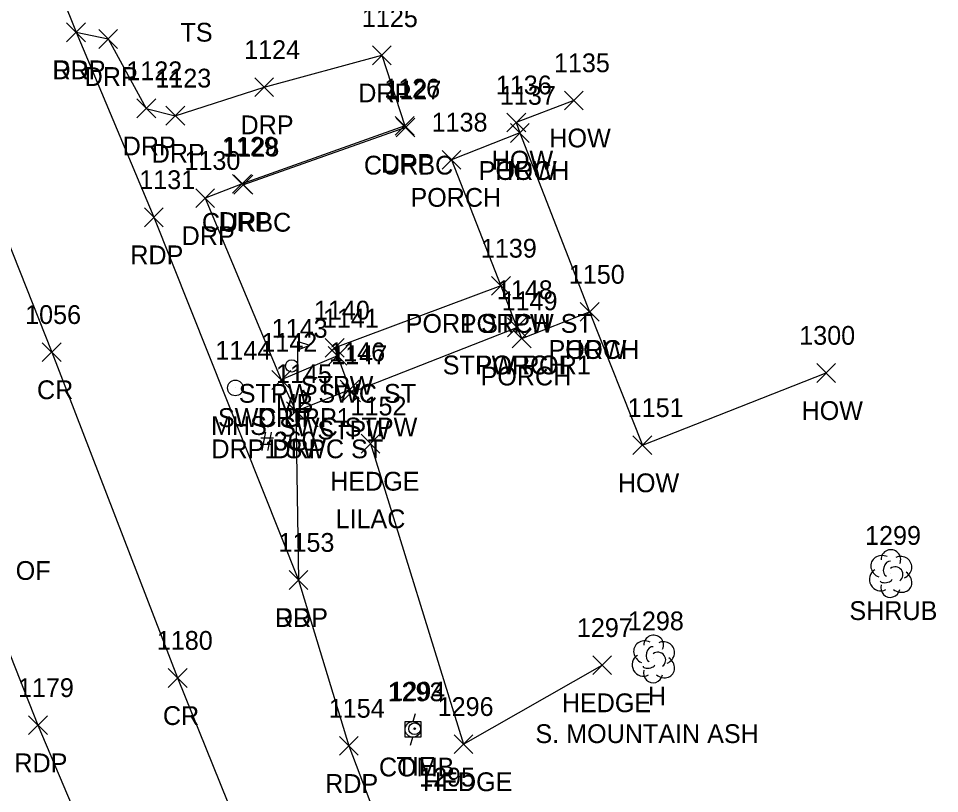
# Model space of a CAD drawing. Extents: x 1651305 to 1654558, y 539481 to 548441.
# Drawn here: x 1654172 to 1654270.1, y 544999.6 to 545082.1 of the extents above; entities that cross this region are included whole.
import ezdxf

# ---------------------------------------------------------------- set-up
doc = ezdxf.new("R2010")
doc.units = 0
for name, color, linetype in [('C_A', 7, 'Continuous'), ('C_C', 7, 'Continuous'), ('C_I', 7, 'Continuous'), ('CBP', 7, 'Continuous'), ('L_A', 7, 'Continuous'), ('L_C', 7, 'Continuous'), ('L_I', 7, 'Continuous'), ('L_TIC', 7, 'Continuous'), ('LAHR', 7, 'Continuous'), ('LBC', 7, 'Continuous'), ('LBF', 7, 'Continuous'), ('LMB', 7, 'Continuous'), ('LSH', 7, 'Continuous'), ('LTD', 7, 'Continuous'), ('P_A', 7, 'Continuous'), ('P_I', 7, 'Continuous'), ('P_TIC', 7, 'Continuous'), ('PET', 7, 'Continuous'), ('PRC', 7, 'Continuous'), ('R_A', 7, 'Continuous'), ('R_I', 7, 'Continuous'), ('R_TIC', 7, 'Continuous'), ('RC', 7, 'Continuous'), ('RDP', 7, 'Continuous'), ('RSW', 7, 'Continuous'), ('S_I', 7, 'Continuous'), ('U_A', 7, 'Continuous'), ('U_I', 7, 'Continuous'), ('UP', 7, 'Continuous'), ('USMH', 7, 'Continuous')]:
    doc.layers.add(name, color=color, linetype=linetype)

msp = doc.modelspace()

# ---------------------------------------------------------------- linework, layer by layer
at = {"layer": 'CBP'}
for radius in [0.625, 0.0833]:
    msp.add_circle((1654214.186, 545006.539), radius, dxfattribs=at)
at = {"layer": 'L_TIC'}
for points in [[(1654230.14, 545072.4), (1654232.14, 545074.4)], [(1654232.14, 545072.4), (1654230.14, 545074.4)], [(1654224.01, 545070.043), (1654226.01, 545072.043)], [(1654226.01, 545070.043), (1654224.01, 545072.043)], [(1654224.388, 545068.937), (1654226.388, 545070.937)], [(1654226.388, 545068.937), (1654224.388, 545070.937)], [(1654224.388, 545068.937), (1654226.388, 545070.937)], [(1654226.388, 545068.937), (1654224.388, 545070.937)], [(1654217.12, 545066.08), (1654219.12, 545068.08)], [(1654219.12, 545066.08), (1654217.12, 545068.08)], [(1654222.373, 545052.669), (1654224.373, 545054.669)], [(1654224.373, 545052.669), (1654222.373, 545054.669)], [(1654222.373, 545052.669), (1654224.373, 545054.669)], [(1654224.373, 545052.669), (1654222.373, 545054.669)], [(1654231.811, 545049.893), (1654233.811, 545051.893)], [(1654233.811, 545049.893), (1654231.811, 545051.893)], [(1654231.811, 545049.893), (1654233.811, 545051.893)], [(1654233.811, 545049.893), (1654231.811, 545051.893)], [(1654224.057, 545048.25), (1654226.057, 545050.25)], [(1654226.057, 545048.25), (1654224.057, 545050.25)], [(1654224.057, 545048.25), (1654226.057, 545050.25)], [(1654226.057, 545048.25), (1654224.057, 545050.25)], [(1654224.58, 545047.071), (1654226.58, 545049.071)], [(1654226.58, 545047.071), (1654224.58, 545049.071)], [(1654204.682, 545046.082), (1654206.682, 545048.082)], [(1654206.682, 545046.082), (1654204.682, 545048.082)], [(1654204.985, 545045.226), (1654206.985, 545047.226)], [(1654206.985, 545045.226), (1654204.985, 545047.226)], [(1654256.976, 545043.395), (1654258.976, 545045.395)], [(1654258.976, 545043.395), (1654256.976, 545045.395)], [(1654206.28, 545041.642), (1654208.28, 545043.642)], [(1654208.28, 545041.642), (1654206.28, 545043.642)], [(1654206.439, 545041.33), (1654208.439, 545043.33)], [(1654208.439, 545041.33), (1654206.439, 545043.33)], [(1654208.495, 545035.878), (1654210.495, 545037.878)], [(1654210.495, 545035.878), (1654208.495, 545037.878)], [(1654237.423, 545035.708), (1654239.423, 545037.708)], [(1654239.423, 545035.708), (1654237.423, 545037.708)], [(1654233.148, 545012.3), (1654235.148, 545014.3)], [(1654235.148, 545012.3), (1654233.148, 545014.3)], [(1654218.387, 545003.9), (1654220.387, 545005.9)], [(1654220.387, 545003.9), (1654218.387, 545005.9)]]:
    msp.add_lwpolyline(points, dxfattribs=at)
at = {"layer": 'LAHR'}
msp.add_lwpolyline([(1654209.495, 545036.878), (1654219.387, 545004.9), (1654234.148, 545013.3)], dxfattribs=at)
at = {"layer": 'LBC'}
msp.add_lwpolyline([(1654231.14, 545073.4), (1654225.01, 545071.043), (1654225.388, 545069.937), (1654232.811, 545050.893), (1654238.423, 545036.708), (1654257.976, 545044.395)], dxfattribs=at)
at = {"layer": 'LBF'}
for points in [[(1654225.388, 545069.937), (1654218.12, 545067.08), (1654223.373, 545053.669), (1654225.057, 545049.25), (1654225.58, 545048.071), (1654232.811, 545050.893)], [(1654223.373, 545053.669), (1654205.682, 545047.082), (1654205.985, 545046.226), (1654207.28, 545042.642), (1654207.439, 545042.33), (1654225.057, 545049.25)]]:
    msp.add_lwpolyline(points, dxfattribs=at)
at = {"layer": 'LMB'}
for p, q in [((1654201.754, 545047.746), (1654203.048, 545047.364)), ((1654201.76, 545045.154), (1654201.759, 545047.748)), ((1654201.759, 545046.846), (1654203.042, 545047.355)), ((1654201.104, 545045.145), (1654201.104, 545045.145))]:
    msp.add_line(p, q, dxfattribs=at)
msp.add_circle((1654201.104, 545045.145), 0.656, dxfattribs=at)
at = {"layer": 'LSH'}
msp.add_line((1654264.824, 545023.109), (1654264.824, 545023.109), dxfattribs=at)
msp.add_line((1654264.824, 545023.109), (1654264.824, 545023.109), dxfattribs=at)
msp.add_arc((1654264.871, 545024.543), 1.047, 335.52715, 180.95627, dxfattribs=at)
for centre, major_axis, ratio, start_param, end_param in [((1654264.032, 545023.775), (1.21, -0.512), 0.895232, 1.570796, 4.712389), ((1654265.866, 545023.692), (-1.141, -0.483), 0.949671, 1.570796, 4.712389), ((1654264.616, 545023.567), (-0.208, -0.792), 0.645439, 3.141593, 6.283185), ((1654265.324, 545022.942), (-0.5, 0.667), 0.989748, 3.141593, 6.283185), ((1654263.741, 545022.4), (0.584, -1.042), 0.959034, 3.141593, 6.283185), ((1654265.824, 545022.276), (-1.09, 0.792), 0.841452, 1.570796, 4.712389), ((1654264.824, 545021.609), (0.265, 1.061), 0.942809, 1.570796, 4.712389), ((1654264.366, 545022.359), (-0.625, -0.083), 0.423636, 0, 3.141593)]:
    msp.add_ellipse(centre, major_axis=major_axis, ratio=ratio, start_param=start_param, end_param=end_param, dxfattribs=at)
at = {"layer": 'LTD'}
msp.add_line((1654239.578, 545014.017), (1654239.578, 545014.017), dxfattribs=at)
msp.add_line((1654239.578, 545014.017), (1654239.578, 545014.017), dxfattribs=at)
msp.add_arc((1654239.625, 545015.451), 1.047, 335.52715, 180.95627, dxfattribs=at)
for centre, major_axis, ratio, start_param, end_param in [((1654238.786, 545014.683), (1.21, -0.512), 0.895232, 1.570796, 4.712389), ((1654240.62, 545014.6), (-1.141, -0.483), 0.949671, 1.570796, 4.712389), ((1654239.37, 545014.475), (-0.208, -0.792), 0.645439, 3.141593, 6.283185), ((1654240.078, 545013.85), (-0.5, 0.667), 0.989748, 3.141593, 6.283185), ((1654238.495, 545013.308), (0.584, -1.042), 0.959034, 3.141593, 6.283185), ((1654240.578, 545013.183), (-1.09, 0.792), 0.841452, 1.570796, 4.712389), ((1654239.12, 545013.266), (-0.625, -0.083), 0.423636, 0, 3.141593), ((1654239.578, 545012.517), (0.265, 1.061), 0.942809, 1.570796, 4.712389)]:
    msp.add_ellipse(centre, major_axis=major_axis, ratio=ratio, start_param=start_param, end_param=end_param, dxfattribs=at)
at = {"layer": 'P_TIC'}
for points in [[(1654177.155, 545079.649), (1654179.155, 545081.649)], [(1654179.155, 545079.649), (1654177.155, 545081.649)], [(1654185.439, 545059.962), (1654187.439, 545061.962)], [(1654187.439, 545059.962), (1654185.439, 545061.962)], [(1654174.565, 545045.61), (1654176.565, 545047.61)], [(1654176.565, 545045.61), (1654174.565, 545047.61)], [(1654200.827, 545021.365), (1654202.827, 545023.365)], [(1654202.827, 545021.365), (1654200.827, 545023.365)], [(1654187.965, 545010.94), (1654189.965, 545012.94)], [(1654189.965, 545010.94), (1654187.965, 545012.94)], [(1654173.104, 545005.911), (1654175.104, 545007.911)], [(1654175.104, 545005.911), (1654173.104, 545007.911)], [(1654206.176, 545003.715), (1654208.176, 545005.715)], [(1654208.176, 545003.715), (1654206.176, 545005.715)]]:
    msp.add_lwpolyline(points, dxfattribs=at)
at = {"layer": 'PET'}
for points in [[(1654139.13, 545176.501), (1654150.393, 545147.194), (1654157.161, 545131.709), (1654170.764, 545099.134), (1654178.155, 545080.649), (1654186.439, 545060.962), (1654201.827, 545022.365), (1654207.176, 545004.715), (1654219.138, 544973.235), (1654242.36, 544920.072), (1654247.532, 544907.575), (1654259.279, 544878.108), (1654268.455, 544853.759), (1654271.522, 544840.232), (1654282.762, 544813.426), (1654295.449, 544782.265), (1654306.751, 544753.721), (1654320.353, 544717.464), (1654325.712, 544702.64)], [(1654112.873, 545166.538), (1654122.035, 545140.208), (1654132.622, 545111.941), (1654135.362, 545108.194), (1654138.441, 545103.483), (1654151.391, 545069.682), (1654150.584, 545065.43), (1654160.56, 545041.116), (1654174.104, 545006.911), (1654181.292, 544989.927), (1654184.888, 544987.01), (1654195.032, 544961.541), (1654207.758, 544928.164), (1654222.993, 544890.413), (1654239.031, 544850.694), (1654252.069, 544818.679), (1654270.718, 544773.03), (1654287.358, 544732.427), (1654297.759, 544708.463), (1654313.88, 544667.099), (1654319.767, 544684.597), (1654325.712, 544702.64)]]:
    msp.add_lwpolyline(points, dxfattribs=at)
at = {"layer": 'PRC'}
msp.add_lwpolyline([(1654126.316, 545171.737), (1654141.33, 545133.412), (1654151.931, 545107.487), (1654165.206, 545072.693), (1654175.565, 545046.61), (1654188.965, 545011.94), (1654198.023, 544989.456), (1654207.449, 544965.611), (1654220.746, 544933.068), (1654235.659, 544895.022), (1654251.308, 544856.189), (1654265.059, 544822.156), (1654283.023, 544778.205), (1654298.758, 544737.492), (1654308.597, 544712.81), (1654319.767, 544684.597)], dxfattribs=at)
at = {"layer": 'R_TIC'}
for points in [[(1654177.155, 545079.649), (1654179.155, 545081.649)], [(1654179.155, 545079.649), (1654177.155, 545081.649)], [(1654180.582, 545078.938), (1654182.582, 545080.938)], [(1654182.582, 545078.938), (1654180.582, 545080.938)], [(1654209.702, 545077.198), (1654211.702, 545079.198)], [(1654211.702, 545077.198), (1654209.702, 545079.198)], [(1654197.172, 545073.799), (1654199.172, 545075.799)], [(1654199.172, 545073.799), (1654197.172, 545075.799)], [(1654184.63, 545071.551), (1654186.63, 545073.551)], [(1654186.63, 545071.551), (1654184.63, 545073.551)], [(1654187.718, 545070.771), (1654189.718, 545072.771)], [(1654189.718, 545070.771), (1654187.718, 545072.771)], [(1654212.13, 545069.697), (1654214.13, 545071.697)], [(1654214.13, 545069.697), (1654212.13, 545071.697)], [(1654212.208, 545069.511), (1654214.208, 545071.511)], [(1654214.208, 545069.511), (1654212.208, 545071.511)], [(1654194.821, 545063.514), (1654196.821, 545065.514)], [(1654196.821, 545063.514), (1654194.821, 545065.514)], [(1654194.963, 545063.43), (1654196.963, 545065.43)], [(1654196.963, 545063.43), (1654194.963, 545065.43)], [(1654190.905, 545062.004), (1654192.905, 545064.004)], [(1654192.905, 545062.004), (1654190.905, 545064.004)], [(1654190.905, 545062.004), (1654192.905, 545064.004)], [(1654192.905, 545062.004), (1654190.905, 545064.004)], [(1654204.985, 545045.226), (1654206.985, 545047.226)], [(1654206.985, 545045.226), (1654204.985, 545047.226)], [(1654198.997, 545042.652), (1654200.997, 545044.652)], [(1654200.997, 545042.652), (1654198.997, 545044.652)], [(1654198.997, 545042.652), (1654200.997, 545044.652)], [(1654200.997, 545042.652), (1654198.997, 545044.652)], [(1654206.28, 545041.642), (1654208.28, 545043.642)], [(1654208.28, 545041.642), (1654206.28, 545043.642)], [(1654200.561, 545039.322), (1654202.561, 545041.322)], [(1654202.561, 545039.322), (1654200.561, 545041.322)], [(1654200.561, 545039.322), (1654202.561, 545041.322)], [(1654202.561, 545039.322), (1654200.561, 545041.322)], [(1654200.827, 545021.365), (1654202.827, 545023.365)], [(1654202.827, 545021.365), (1654200.827, 545023.365)]]:
    msp.add_lwpolyline(points, dxfattribs=at)
at = {"layer": 'RC'}
msp.add_lwpolyline([(1654213.208, 545070.511), (1654195.963, 545064.43)], dxfattribs=at)
at = {"layer": 'RDP'}
for points in [[(1654178.155, 545080.649), (1654181.582, 545079.938), (1654185.63, 545072.551), (1654188.718, 545071.771), (1654198.172, 545074.799), (1654210.702, 545078.198), (1654213.13, 545070.697), (1654195.821, 545064.514), (1654191.905, 545063.004)], [(1654191.905, 545063.004), (1654199.997, 545043.652), (1654201.561, 545040.322), (1654201.827, 545022.365)]]:
    msp.add_lwpolyline(points, dxfattribs=at)
at = {"layer": 'RSW'}
for points in [[(1654205.985, 545046.226), (1654199.997, 545043.652)], [(1654201.561, 545040.322), (1654207.28, 545042.642)]]:
    msp.add_lwpolyline(points, dxfattribs=at)
at = {"layer": 'UP'}
for p, q in [((1654214.256, 545008.133), (1654214.006, 545007.3)), ((1654213.172, 545005.633), (1654213.172, 545007.3)), ((1654213.172, 545007.3), (1654214.839, 545007.3)), ((1654214.839, 545007.3), (1654214.839, 545005.633)), ((1654214.006, 545006.466), (1654214.006, 545006.466)), ((1654214.839, 545005.633), (1654213.172, 545005.633)), ((1654213.756, 545004.8), (1654214.006, 545005.633))]:
    msp.add_line(p, q, dxfattribs=at)
msp.add_circle((1654214.006, 545006.466), 0.833, dxfattribs=at)
at = {"layer": 'USMH'}
for p, q in [((1654195.109, 545042.8), (1654195.109, 545042.8)), ((1654195.942, 545042.8), (1654195.942, 545042.8))]:
    msp.add_line(p, q, dxfattribs=at)
msp.add_circle((1654195.109, 545042.8), 0.833, dxfattribs=at)

# ---------------------------------------------------------------- texts
at = {"layer": 'C_A'}
msp.add_text('TIE', height=2, dxfattribs=at).set_placement((1654212.265, 545001.539))
at = {"layer": 'C_C'}
msp.add_text('TIE DIST=91.20 TOP CENTER OF', height=2, dxfattribs=at).set_placement((1654133.759, 545022.379))
at = {"layer": 'C_I'}
msp.add_text('1294', height=2, dxfattribs=at).set_placement((1654211.494, 545009.539))
at = {"layer": 'L_A'}
for s, p in [('TS', (1654189.27, 545079.654)), ('HOW', (1654228.526, 545068.4)), ('HOW', (1654222.396, 545066.043)), ('PORCH', (1654221.01, 545064.937)), ('HOW', (1654222.774, 545064.937)), ('PORCH', (1654213.742, 545062.08)), ('POR1 STPW ST', (1654213.239, 545048.669)), ('PORCH', (1654218.995, 545048.669)), ('PORCH', (1654228.433, 545045.893)), ('HOW', (1654230.197, 545045.893)), ('STPW POR1', (1654217.183, 545044.25)), ('PORCH', (1654220.679, 545044.25)), ('PORCH', (1654221.202, 545043.071)), ('STPW SWC ST', (1654195.474, 545041.226)), ('STPW', (1654202.075, 545042.082)), ('MB', (1654199.412, 545040.145)), ('HOW', (1654255.362, 545039.395)), ('SWC STPW', (1654199.768, 545037.642)), ('STPW', (1654203.833, 545037.33)), ('HEDGE', (1654205.196, 545031.878)), ('HOW', (1654235.809, 545031.708)), ('SHRUB', (1654260.454, 545018.109)), ('H', (1654239.011, 545009.017)), ('HEDGE', (1654229.849, 545008.3)), ('HEDGE', (1654215.088, 544999.9))]:
    msp.add_text(s, height=2, dxfattribs=at).set_placement(p)
at = {"layer": 'L_C'}
for s, p in [('#360', (1654197.711, 545036.145)), ('LILAC', (1654205.771, 545027.878)), ('S. MOUNTAIN ASH', (1654227.043, 545005.017))]:
    msp.add_text(s, height=2, dxfattribs=at).set_placement(p)
at = {"layer": 'L_I'}
for s, p in [('1135', (1654229.015, 545076.4)), ('1136', (1654222.829, 545074.043)), ('1137', (1654223.262, 545072.937)), ('1137', (1654223.262, 545072.937)), ('1138', (1654215.994, 545070.08)), ('1139', (1654221.239, 545056.669)), ('1139', (1654221.239, 545056.669)), ('1150', (1654230.599, 545053.893)), ('1150', (1654230.599, 545053.893)), ('1148', (1654222.931, 545052.25)), ('1148', (1654222.931, 545052.25)), ('1149', (1654223.446, 545051.071)), ('1140', (1654203.469, 545050.082)), ('1141', (1654204.427, 545049.226)), ('1143', (1654198.979, 545048.145)), ('1300', (1654255.118, 545047.395)), ('1146', (1654205.099, 545045.642)), ('1147', (1654205.313, 545045.33)), ('1152', (1654207.369, 545039.878)), ('1151', (1654236.865, 545039.708)), ('1299', (1654262.124, 545026.109)), ('1298', (1654236.885, 545017.017)), ('1297', (1654231.455, 545016.3)), ('1296', (1654216.639, 545007.9))]:
    msp.add_text(s, height=2, dxfattribs=at).set_placement(p)
at = {"layer": 'P_A'}
for s, p in [('RDP', (1654175.643, 545075.649)), ('RDP', (1654183.927, 545055.962)), ('CR', (1654173.998, 545041.61)), ('RDP', (1654199.315, 545017.365)), ('CR', (1654187.398, 545006.94)), ('RDP', (1654171.592, 545001.911)), ('RDP', (1654204.664, 544999.715))]:
    msp.add_text(s, height=2, dxfattribs=at).set_placement(p)
at = {"layer": 'P_I'}
for s, p in [('1131', (1654184.88, 545063.962)), ('1056', (1654172.739, 545049.61)), ('1153', (1654199.701, 545025.365)), ('1180', (1654186.753, 545014.94)), ('1179', (1654171.971, 545009.911)), ('1154', (1654205.05, 545007.715))]:
    msp.add_text(s, height=2, dxfattribs=at).set_placement(p)
at = {"layer": 'R_A'}
for s, p in [('DRP', (1654175.643, 545075.649)), ('DRP', (1654179.07, 545074.938)), ('DRP', (1654208.19, 545073.198)), ('DRP', (1654195.66, 545069.799)), ('DRP', (1654183.118, 545067.551)), ('DRP', (1654186.206, 545066.771)), ('DRP', (1654210.618, 545065.697)), ('CURBC', (1654208.79, 545065.511)), ('CURBC', (1654191.546, 545059.43)), ('DRP', (1654193.309, 545059.514)), ('DRP', (1654189.393, 545058.004)), ('DRP', (1654189.393, 545058.004)), ('STPW SWC ST', (1654195.474, 545041.226)), ('SWC DRP1', (1654193.257, 545038.652)), ('DRP', (1654197.485, 545038.652)), ('SWC STPW', (1654199.768, 545037.642)), ('DRP1 SWC ST', (1654192.561, 545035.322)), ('DRP', (1654199.049, 545035.322)), ('DRP', (1654199.315, 545017.365))]:
    msp.add_text(s, height=2, dxfattribs=at).set_placement(p)
at = {"layer": 'R_I'}
for s, p in [('1125', (1654208.576, 545081.198)), ('1124', (1654196.046, 545077.799)), ('1122', (1654183.504, 545075.551)), ('1123', (1654186.592, 545074.771)), ('1126', (1654210.949, 545073.697)), ('1127', (1654211.082, 545073.511)), ('1129', (1654193.687, 545067.514)), ('1128', (1654193.837, 545067.43)), ('1130', (1654189.693, 545066.004)), ('1130', (1654189.693, 545066.004)), ('1141', (1654204.427, 545049.226)), ('1142', (1654197.872, 545046.652)), ('1142', (1654197.872, 545046.652)), ('1146', (1654205.099, 545045.642)), ('1145', (1654199.435, 545043.322)), ('1145', (1654199.435, 545043.322)), ('1153', (1654199.701, 545025.365))]:
    msp.add_text(s, height=2, dxfattribs=at).set_placement(p)
at = {"layer": 'S_I'}
msp.add_text('1295', height=2, dxfattribs=at).set_placement((1654214.666, 545000.391))
at = {"layer": 'U_A'}
for s, p in [('MHS', (1654192.526, 545037.8)), ('COMB', (1654210.392, 545001.466))]:
    msp.add_text(s, height=2, dxfattribs=at).set_placement(p)
at = {"layer": 'U_I'}
for s, p in [('1144', (1654192.983, 545045.8)), ('1293', (1654211.313, 545009.466))]:
    msp.add_text(s, height=2, dxfattribs=at).set_placement(p)

doc.saveas('drawing.dxf')
